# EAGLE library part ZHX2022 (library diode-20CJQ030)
ZILOG ZHX2022 FIR Transceiver Description: Whether you need to mount the IrDA transceiver so that its communication is parallel or perpendicular to the plane of the PCB, the ZiLOG ZHX2022 is the solution for applications in portable products, such as USB Adapters, notebook PCs, printers, mobile phones, digital cameras, handheld devices, or personal data assistants (PDAs). Designed to support all IrDA data rates up to 4 Mbits/second as well as LocalTalk? and Sharp ASK? modes, the transceiver combines an infrared emitting diode (IRED) emitter, a PIN photodiode detector, an IRED driver, and an integrated AGC (Automatic Gain Control) and amplification receive circuit in a single, miniature package. The ZiLOG ZHX2022 provides an efficient implementation of the IrDA-Data 1.4 standard in a small footprint format. Application circuit space is also minimized, as only three external components (current-limiting resistor, terminating resistor, and a decoupling capacitor) are required to implement a complete IrDA transceiver solution. The ZHX2022 is capable of both mode select and legacy-mode bandwidth switching. Features : Supply voltage 2.7 V to 5.5 V, operating idle current (receive mode) Please send any comments to: messi@users.sourceforge.net
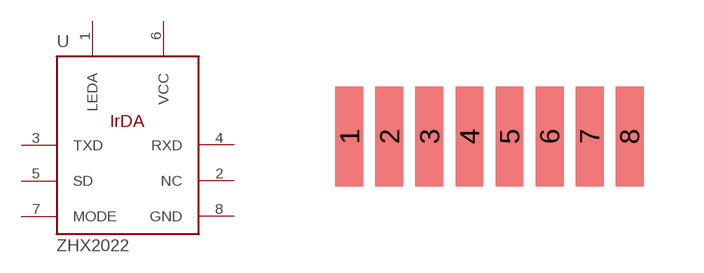
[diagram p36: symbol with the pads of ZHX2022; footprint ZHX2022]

Designator prefix U

## ZHX2022  [ZHX2022]
1  LEDA  pwr
2  NC  nc
3  TXD  in
4  RXD  out
5  SD  in
6  VCC  pwr
7  MODE
8  GND  pwr

## Footprint ZHX2022 (pad centres in mm)
Zilog packaging for the IrDA device ZHX1810 Please send any comments to: messi@users.sourceforge.net
smd 0.7 x 2.5: 1 -3.5,0; 2 -2.5,0; 3 -1.5,0; 4 -0.5,0; 5 0.5,0; 6 1.5,0; 7 2.5,0; 8 3.5,0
